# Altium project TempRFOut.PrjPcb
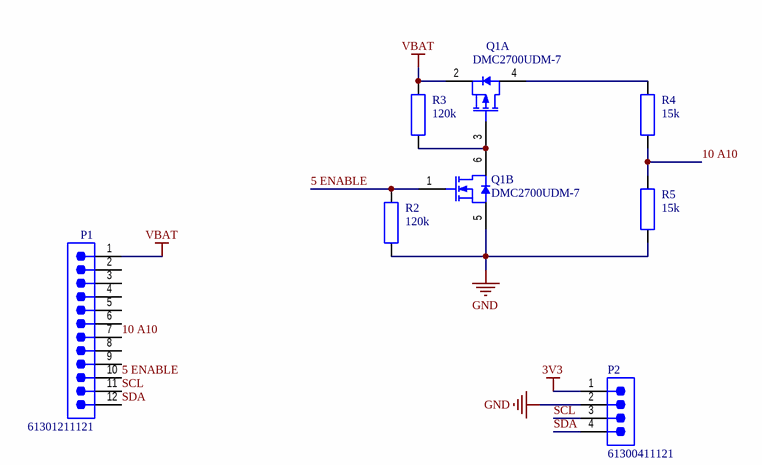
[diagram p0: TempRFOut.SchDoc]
F_DrawnBy: LSR; F_Project: BT_Endurance; F_Revision: 1
1 sheet, 7 parts. Net scope: global (net labels, ports and power ports of the same name join across sheets).
Board file: TempRFOut.PcbDoc

## Sheet TempRFOut.SchDoc
size A4; DrawnBy: LSR; Engineer: CW; SheetNumber: 1; SheetTotal: 1; PageSetup: Record=PageOptions¦CenterHorizontal=True¦CenterVertical=True¦PrintScale=1.00¦XCorrection=1.00¦YCorrection=1.00¦PrintKind=0¦BorderSize=5000000¦LeftOffset=0¦BottomOffset=0¦Orientation=2¦PaperLength=1000¦PaperWidth=1000¦Scale=100¦PaperSource=7¦PrintQuality=-3¦MediaType=1¦DitherType=10¦PrintScaleMode=1¦PaperKind=A4¦PaperIndex=9

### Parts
P1  61301211121  [61301211121]
P2  61300411121  [61300411121]
Q1  DMC2700UDM-7  [FAIR-SOT23-6_V]  (parts A,B of 2)
R2  120k  [0603]
R3  120k  [0603]
R4  15k  [0603]
R5  15k  [0603]

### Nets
3V3: P2.1
GND: P2.2 Q1.5(S) R2.1 R5.1
VBAT: P1.1 Q1.2(S) R3.2
5 ENABLE: P1.10 Q1.1(G) R2.2
10 A10: P1.7 R4.1 R5.2
SCL: P1.11 P2.3
SDA: P1.12 P2.4
NetQ1_3: Q1.3(G) Q1.6(D) R3.1
NetQ1_4: Q1.4(D) R4.2

Not connected (* = marked no-connect by the designer): P1 2 3 4 5 6 8 9

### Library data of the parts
P1 = CMP-1502-01086-4: THT Vertical Pin Header WR-PHD, Pitch 2.54 mm, Single Row, 12 pins; Connector Type: Male Pin; Current Rating: 3A; Gender: Male; Contact Resistance: 20mΩ; Operating Supply Voltage: 250V; Number of Positions: 12; Pitch: 2.54mm
P2 = CMP-1502-01064-4: THT Vertical Pin Header WR-PHD, Pitch 2.54 mm, Single Row, 4 pins; Connector Type: Male Pin; Gender: Male; Current Rating: 3A; Number of Positions: 4; Operating Supply Voltage: 250V; Contact Resistance: 20mΩ; Pitch: 2.54mm
Q1 = CMP-2000-04939-1: Dual N & P-Channel 2.5 V Specified PowerTrench(TM) MOSFET, -55 to 150 degC, 6-Pin SOT-23, RoHS, Tape and Reel; Manufacturer: Fairchild; Typical Rise Time: 9@NChannel; Rad Hard: No; Maximum Drain Source Voltage: 20V; Typical Fall Time: 3@NChannel; Typical Turn-On Delay Time: 5@NChannel; Maximum Continuous Drain Current: 2.7@NChannel; Typical Turn-Off Delay Time: 12@NChannel; RDS-on: 80@4.5V@NChannel; Channel Mode: Enhancement; Maximum Gate Source Voltage: ±8V; Package Version: Rev. 5, 05/2015
R2-R5 = R: Resistor

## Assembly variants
MassProduction: all parts fitted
